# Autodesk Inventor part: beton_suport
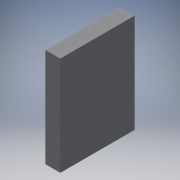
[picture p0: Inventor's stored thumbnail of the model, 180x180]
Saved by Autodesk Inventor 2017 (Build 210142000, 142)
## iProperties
Created: 2017-11
Part Number: beton_suport
Material: GFRC
Document SubType Name: Modeling
Designer: iusti
Density: 1.7 g/cm^3
Appearance: Flat - Polished Gray
Author: iusti
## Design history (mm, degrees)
sketch "Sketch1"
  geometry: L1 (750, 1000)-(-750, 1000); L2 (-750, 1000)-(-750, -1000); L3 (-750, -1000)-(750, -1000); L4 (750, -1000)-(750, 1000); L5 (750, 1000)-(-750, -1000); L6 (-750, 1000)-(750, -1000); 1 further point
  constraints: 12 end point, 2 midpoint, 2 parallel, 1 horizontal, 1 perpendicular
  dimensions: "d0" = 2000 distance of L3.end L1.start; "d1" = 1500 distance of L1.start L1.end
extrude "Extrusion1" new body sketch "Sketch1" distance "d2" = 300; taper "d3" = 0 deg
body "Solid1"
